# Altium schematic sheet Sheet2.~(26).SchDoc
size A3
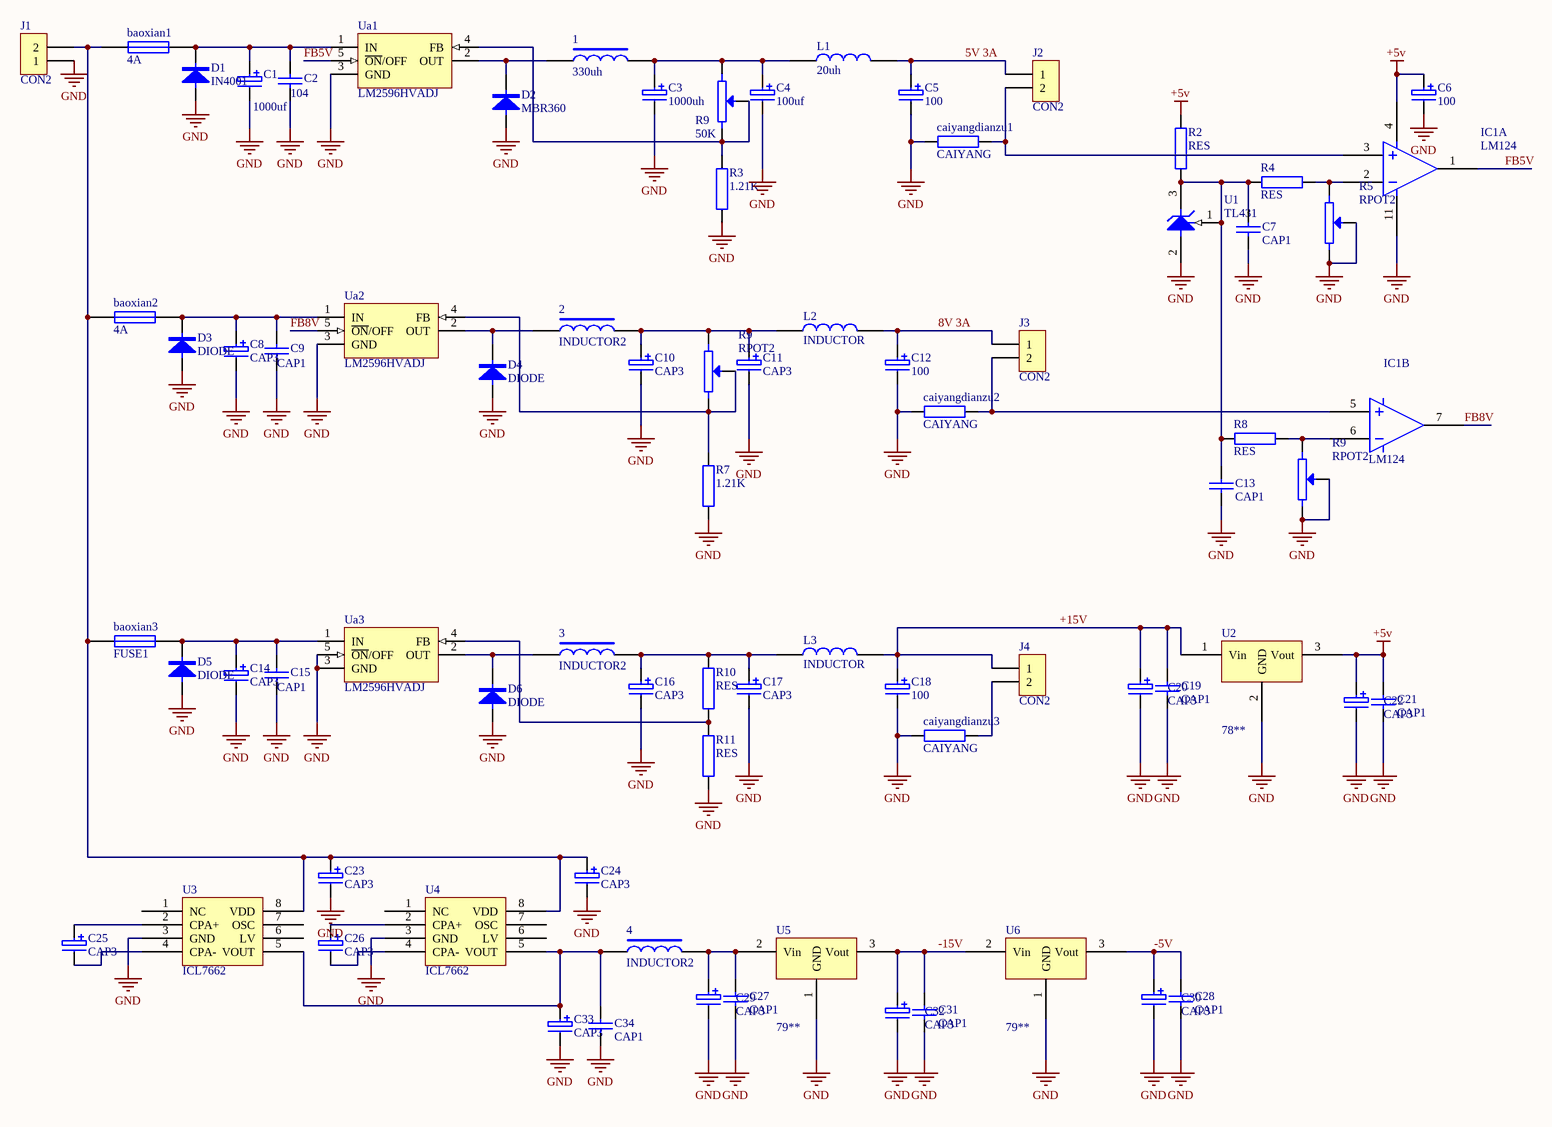
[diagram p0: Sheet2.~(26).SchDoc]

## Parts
(Parts that share a designator on the sheet are numbered #1, #2 ... from top to bottom, then left to right.)
1  330uh
2  INDUCTOR2
3  INDUCTOR2
4  INDUCTOR2
baoxian1  4A  [RAD0.5]
baoxian2  4A  [RAD0.5]
baoxian3  FUSE1  [RAD0.5]
C1  1000uf  [RB2]
C2  104  [RAD0.2]
C3  1000uh  [RB3]
C4  100uf  [RB3]
C5  100  [RB1]
C6  100  [RB1]
C7  CAP1  [RAD0.15]
C8  CAP3  [RB2]
C9  CAP1  [RAD0.2]
C10  CAP3  [RB3]
C11  CAP3  [RB3]
C12  100  [RB1]
C13  CAP1  [RAD0.15]
C14  CAP3  [RB2]
C15  CAP1  [RAD0.2]
C16  CAP3  [RB3]
C17  CAP3  [RB3]
C18  100  [RB1]
C19  CAP1  [RAD0.15]
C20  CAP3  [RB3]
C21  CAP1  [RAD0.15]
C22  CAP3  [RB3]
C23  CAP3  [RB3]
C24  CAP3  [RB3]
C25  CAP3  [RB3]
C26  CAP3  [RB3]
C27  CAP1  [RAD0.15]
C28  CAP1  [RAD0.15]
C29  CAP3  [RB3]
C30  CAP3  [RB3]
C31  CAP1  [RAD0.15]
C32  CAP3  [RB3]
C33  CAP3  [RB3]
C34  CAP1  [RAD0.15]
caiyangdianzu1  CAIYANG  [AXIAL0.8]
caiyangdianzu2  CAIYANG  [AXIAL0.8]
caiyangdianzu3  CAIYANG  [AXIAL0.8]
D1  IN4001  [DIODE0.4]
D2  MBR360  [DIODE0.2]
D3  DIODE  [DIODE0.4]
D4  DIODE  [DIODE0.2]
D5  DIODE  [DIODE0.4]
D6  DIODE  [DIODE0.2]
IC1  LM124  [DIP-14]  (parts A,B of 4)
J1  CON2  [BCON2]
J2  CON2  [BCON2]
J3  CON2  [BCON2]
J4  CON2  [BCON2]
L1  20uh  [LHF440]
L2  INDUCTOR  [LHF440]
L3  INDUCTOR  [LHF440]
R2  RES  [AXIAL0.3]
R3  1.21K  [AXIAL0.3]
R4  RES  [AXIAL0.3]
R5  RPOT2  [VR5]
R7  1.21K  [AXIAL0.3]
R8  RES  [AXIAL0.3]
R9#1  50K  [VR5]
R9#2  RPOT2  [VR5]
R9#3  RPOT2  [VR5]
R10  RES  [AXIAL0.3]
R11  RES  [AXIAL0.3]
U1  TL431  [TO92B]
U2  78**  [TO257V]
U3  ICL7662  [DIP-8]
U4  ICL7662  [DIP-8]
U5  79**  [TO257V]
U6  79**  [TO257V]
Ua1  LM2596HVADJ  [SIP-5]
Ua2  LM2596HVADJ  [SIP-5]
Ua3  LM2596HVADJ  [SIP-5]

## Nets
+5v: C6.1 C21.1 C22.1 IC1.4 R2.2 U2.3(Vout)
GND: C1.2 C2.2 C3.2 C4.2 C5.2 C6.2 C7.2 C8.2 C9.2 C10.2 C11.2 C12.2 C13.2 C14.2 C15.2 C16.2 C17.2 C18.2 C19.2 C20.2 C21.2 C22.2 C23.2 C24.2 C27.2 C28.2 C29.2 C30.2 C31.2 C32.2 C33.2 C34.2 caiyangdianzu1.2 caiyangdianzu2.2 caiyangdianzu3.2 D1.1 D2.1 D3.1 D4.1 D5.1 D6.1 IC1.11 J1.1 R3.1 R5.2(VT) R5.3 R7.1 R9#3.2(VT) R9#3.3 R11.1 U1.2(A) U2.2(GND) U3.3(GND) U4.3(GND) U5.1(GND) U6.1(GND) Ua1.3(GND) Ua2.3(GND) Ua3.3(GND) Ua3.5(~{ON}/OFF)
5V 3A: C5.1 J2.1 L1.2
8V 3A: C12.1 J3.1 L2.2
+15V: C18.1 C19.1 C20.1 J4.1 L3.2 U2.1(Vin)
-5V: C28.1 C30.1 U6.3(Vout)
-15V: C31.1 C32.1 U5.3(Vout) U6.2(Vin)
FB5V: IC1.1 Ua1.5(~{ON}/OFF)
FB8V: IC1.7 Ua2.5(~{ON}/OFF)
Net1_1: 1.1 D2.2 Ua1.2(OUT)
Net1_2: 1.2 C3.1 C4.1 L1.1 R9#1.1
Net2_1: 2.1 D4.2 Ua2.2(OUT)
Net2_2: 2.2 C10.1 C11.1 L2.1 R9#2.1
Net3_1: 3.1 D6.2 Ua3.2(OUT)
Net3_2: 3.2 C16.1 C17.1 L3.1 R10.2
Net4_1: 4.1 C33.1 C34.1 U3.5(VOUT) U4.5(VOUT)
Net4_2: 4.2 C27.1 C29.1 U5.2(Vin)
Netbaoxian1_1: baoxian1.1 C1.1 C2.1 D1.2 Ua1.1(IN)
Netbaoxian1_2: baoxian1.2 baoxian2.2 baoxian3.2 C23.1 C24.1 J1.2 U3.8(VDD) U4.8(VDD)
Netbaoxian2_1: baoxian2.1 C8.1 C9.1 D3.2 Ua2.1(IN)
Netbaoxian3_1: baoxian3.1 C14.1 C15.1 D5.2 Ua3.1(IN)
NetC7_1: C7.1 C13.1 R2.1 R4.1 R8.1 U1.1(REF) U1.3(K)
NetC25_1: C25.1 U3.2(CPA+)
NetC25_2: C25.2 U3.4(CPA-)
NetC26_1: C26.1 U4.2(CPA+)
NetC26_2: C26.2 U4.4(CPA-)
Netcaiyangdianzu1_1: caiyangdianzu1.1 IC1.3 J2.2
Netcaiyangdianzu2_1: caiyangdianzu2.1 IC1.5 J3.2
Netcaiyangdianzu3_1: caiyangdianzu3.1 J4.2
NetIC1_2: IC1.2 R4.2 R5.1
NetIC1_6: IC1.6 R8.2 R9#3.1
NetR3_2: R3.2 R9#1.2(VT) R9#1.3 Ua1.4(FB)
NetR7_2: R7.2 R9#2.2(VT) R9#2.3 Ua2.4(FB)
NetR10_1: R10.1 R11.2 Ua3.4(FB)

Not connected (* = marked no-connect by the designer): U3 1(NC) 6(LV) 7(OSC); U4 1(NC) 6(LV) 7(OSC)

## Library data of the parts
1 = INDUCTOR2
baoxian1-baoxian3 = FUSE1: Fuse
C1 C3-C6 C12 C18 = CAP3
C2 = CAP1
caiyangdianzu1-caiyangdianzu3 R3 R7 = RES
D1 D2 = DIODE
J1-J4 = CON2: Connector
L1 = INDUCTOR
R5 R9#1-R9#3 = RPOT2: Potentiometer
U1 = TL431: Programmable Voltage Reference
Ua1-Ua3 = LM2596T-5.0: Simple Switcher Power Converter 150 kHz 3A Step Down Voltage Regulator; PackageDocument: 2000; Note: Tab is connected to GND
